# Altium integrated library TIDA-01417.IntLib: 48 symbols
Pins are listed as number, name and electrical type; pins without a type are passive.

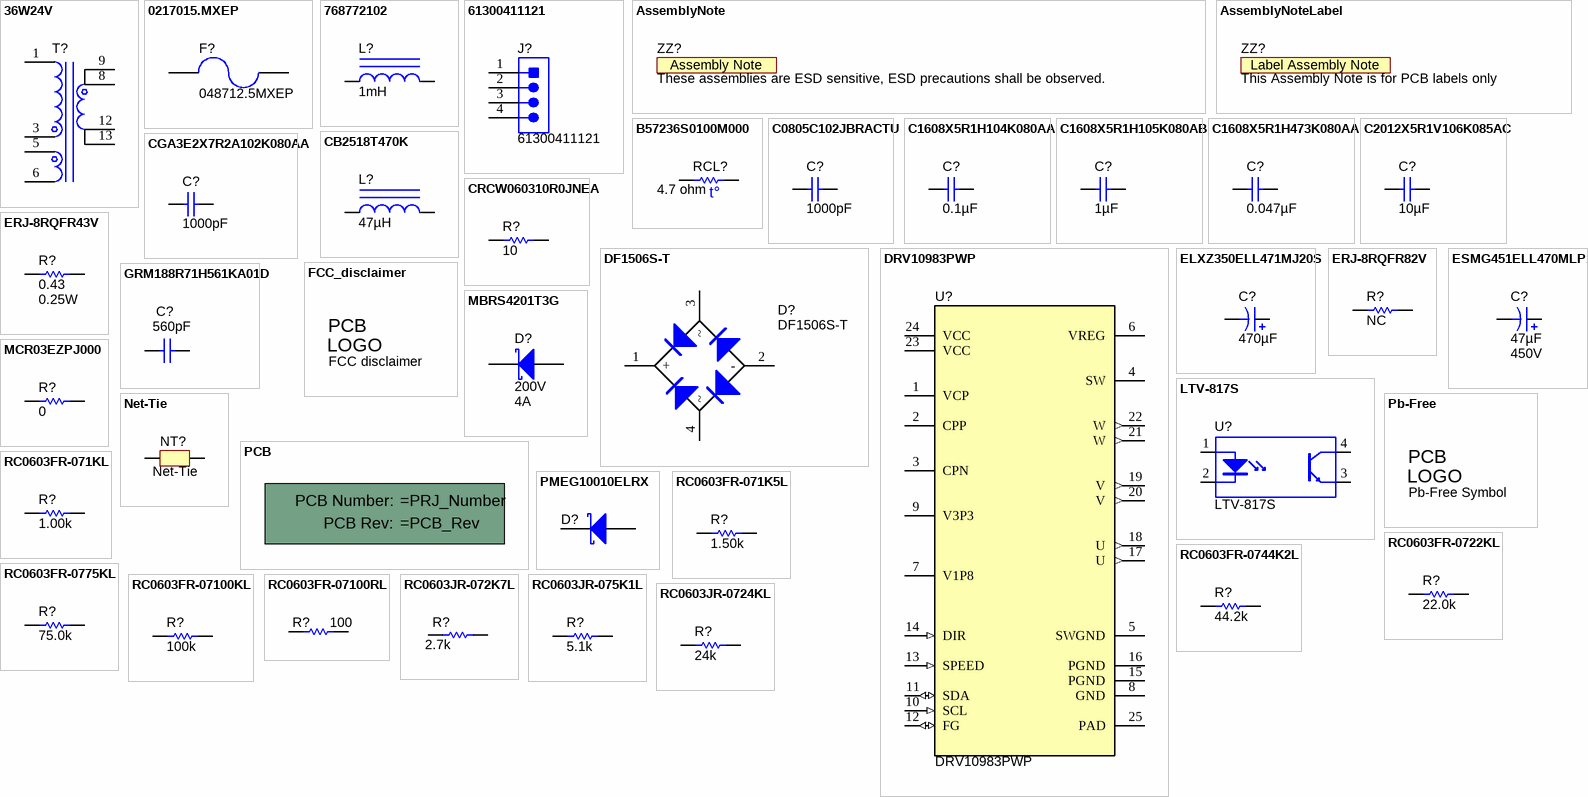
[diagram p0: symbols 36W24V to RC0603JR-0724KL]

## 36W24V
designator T?, comment Used in BOM report  (value not drawn)
SymbolVersion: use current date i.e. 2008-05-20; SymbolCreator: Use a-id; CompType: Used in some BOM reports.  Useful for finding later.; U/M: EA, IN, or GM
footprint PCBComponent_1
pins: 1, 3, 5, 6, 8, 9, 12, 13

## 0217015.MXEP
designator F?, comment 048712.5MXEP
FUSE 420VAC/DC 5X20 FA PT 12.5A; Manufacturer: Littelfuse; VDC_V: 250; Irating_A: 8; Rtyp_Ohm: 0.04; MeltingTyp: 617.135
footprint Fuse_217_015
footprint Fuse_217_015_Verical
pins: 1, 2

## 768772102
designator L?  ValueDisplayed: 1mH  (hidden comment: 768772102)
Inductor, Shielded Drum Core, Metal Composite, 1 mH, 0.5 A, 1.7 ohm, TH; Manufacturer: Wurth Elektronik; Value: 1mH; Ind_H: 1.0E-3; Imax_A: 0.5; Irms: 0.5A @ 40C rise; Isat: 0.55A @ 10% inductance drop; DCR_ohm: 1.7; Value1: 1.7 ohm; Value2: 0.5A; SizeAreaWB_mm2: 96.04; SizeArea_mm2: 60.84; SizeX_mm: 7.8; SizeZ_mm: 10; AEC Category: Q200
signal-integrity model Inductor
simulation model Inductor
footprint WE-TI_8095
pins: 1, 2

## 61300411121
designator J?
Header, 2.54 mm, 4x1, Gold, TH; Manufacturer: Wurth Elektronik; SymbolCreator: a0412235
footprint WURTH_61300411121
pins: 1, 2, 3, 4

## AssemblyNote
designator ZZ?, comment These assemblies are ESD sensitive, ESD precautions shall be observed.  (no BOM)
SymbolCreator: codlsc; CompType: AssemblyNote
footprint AssemblyNote

## AssemblyNoteLabel
designator ZZ?, comment This Assembly Note is for PCB labels only  (no BOM)
SymbolCreator: a0412235
footprint AssemblyNoteLabel

## B57236S0100M000
designator RCL?, comment value 4.7 ohm  (hidden comment: B57236S479M)
ICL 4.7 OHM 20% 4.6A 11.51MM; Manufacturer: EPCOS (TDK); CompType: ThermistorNTC; Tolerance_%: 20; Power_W: 2.1; U/M: EA; TaMin_C: -55; TaMax_C: 170
footprint THERM_B57236S0 (EPCOS)
pins: 1, 2

## C0805C102JBRACTU
designator C?  ValueDisplayed: 1000pF  (hidden comment: C0805C102JBRACTU)
CAP, CERM, 1000 pF, 630 V, +/- 5%, X7R, 0805; Manufacturer: Kemet; Polarized: N; CompType: Capacitor; Value: 1000pF; U/M: EA; Cap_F: 0.000000001; Tolerance_%: 5; Value1: Unknown; VDC_V: 630; Value2: 630V; TaMin_C: -55; TaMax_C: 125; Cap_Case: 0805; SizeArea_mm2: 2.5; SizeAreaWB_mm2: 6.75; SizeX_mm: 2; SizeY_mm: 1.25; SizeZ_mm: 1.45; AEC Category: Q200
signal-integrity model Cap
simulation model Cap
footprint 0805_HV
footprint 0805_HV1
footprint 0805
footprint 0805M
footprint 0805L
pins: 1, 2

## C1608X5R1H104K080AA
designator C?  ValueDisplayed: 0.1µF  (hidden comment: C1608X5R1H104K080AA)
CAP, CERM, 0.1 µF, 50 V, +/- 10%, X5R, 0603; Manufacturer: TDK; Polarized: N; CompType: Capacitor; Value: 0.1uF; U/M: EA; Cap_F: 0.0000001; Tolerance_%: 10; ESR_ohm: 0.0296; Value1: 0.0296 ohm; VDC_V: 50; Value2: 50V; IRMS_A: 0.97199; TaMin_C: -55; TaMax_C: 85; Cap_Case: 0603; SizeArea_mm2: 1.28; SizeAreaWB_mm2: 4.68; SizeX_mm: 1.6; SizeY_mm: 0.8; SizeZ_mm: 1; AEC Category: Q200
signal-integrity model Cap
simulation model Cap
footprint 0603
footprint 0603M
footprint 0603L
footprint 0603_HV
footprint 0603S
pins: 1, 2

## C1608X5R1H105K080AB
designator C?  ValueDisplayed: 1µF  (hidden comment: C1608X5R1H105K080AB)
CAP, CERM, 1 µF, 50 V, +/- 10%, X5R, 0603; Manufacturer: TDK; Polarized: N; CompType: Capacitor; Value: 1uF; U/M: EA; Cap_F: 0.000001; Tolerance_%: 10; ESR_ohm: 0.005522; Value1: 0.005522 ohm; VDC_V: 50; Value2: 50V; IRMS_A: 2.21617; TaMin_C: -55; TaMax_C: 85; Cap_Case: 0603; SizeArea_mm2: 1.28; SizeAreaWB_mm2: 4.68; SizeX_mm: 1.6; SizeY_mm: 0.8; SizeZ_mm: 1; AEC Category: Q200
signal-integrity model Cap
simulation model Cap
footprint 0603
footprint 0603M
footprint 0603L
footprint 0603_HV
footprint 0603S
pins: 1, 2

## C1608X5R1H473K080AA
designator C?  ValueDisplayed: 0.047µF  (hidden comment: C1608X5R1H473K080AA)
CAP, CERM, 0.047 µF, 50 V, +/- 10%, X5R, 0603; Manufacturer: TDK; Polarized: N; CompType: Capacitor; Value: 0.047uF; U/M: EA; Cap_F: 0.000000047; Tolerance_%: 10; ESR_ohm: 0.049007; Value1: 0.049007 ohm; VDC_V: 50; Value2: 50V; IRMS_A: 0.767528; TaMin_C: -55; TaMax_C: 85; Cap_Case: 0603; SizeArea_mm2: 1.28; SizeAreaWB_mm2: 4.68; SizeX_mm: 1.6; SizeY_mm: 0.8; SizeZ_mm: 1; AEC Category: Q200
signal-integrity model Cap
simulation model Cap
footprint 0603
footprint 0603M
footprint 0603L
footprint 0603_HV
footprint 0603S
pins: 1, 2

## C2012X5R1V106K085AC
designator C?  ValueDisplayed: 10µF  (hidden comment: C2012X5R1V106K085AC)
CAP, CERM, 10 µF, 35 V, +/- 10%, X5R, 0805; Manufacturer: TDK; Polarized: N; CompType: Capacitor; Value: 10uF; U/M: EA; Cap_F: 0.00001; Tolerance_%: 10; ESR_ohm: 0.002818; Value1: 0.002818 ohm; VDC_V: 35; Value2: 35V; IRMS_A: 3.88676; TaMin_C: -55; TaMax_C: 85; Cap_Case: 0805; SizeArea_mm2: 2.5; SizeAreaWB_mm2: 6.75; SizeX_mm: 2; SizeY_mm: 1.25; SizeZ_mm: 1.45; AEC Category: Q200
signal-integrity model Cap
simulation model Cap
footprint 0805_HV
footprint 0805_HV1
footprint 0805
footprint 0805M
footprint 0805L
pins: 1, 2

## CB2518T470K
designator L?  ValueDisplayed: 47µH  (hidden comment: CB2518T470K)
Inductor, Wirewound, Ferrite, 47 µH, 0.11 A, 1.235 ohm, SMD; Manufacturer: Taiyo Yuden; Value: 47uH; Ind_H: 47.0E-6; Imax_A: 0.11; Irms: 0.42A @ 40C rise; Isat: 0.11A @ 30% inductance drop; DCR_ohm: 1.235; Value2: 0.11A; SizeAreaWB_mm2: 9.8; SizeArea_mm2: 4.5; SizeX_mm: 2.5; SizeY_mm: 1.8; SizeZ_mm: 2; AEC Category: Q200
signal-integrity model Inductor
simulation model Inductor
footprint IND_CB2518
pins: 1, 2

## CGA3E2X7R2A102K080AA
designator C?  ValueDisplayed: 1000pF  (hidden comment: CGA3E2X7R2A102K080AA)
CAP, CERM, 1000 pF, 100 V, +/- 10%, X7R, AEC-Q200 Grade 1, 0603; Manufacturer: TDK; Polarized: N; CompType: Capacitor; Value: 1000pF; U/M: EA; Cap_F: 0.000000001; Tolerance_%: 10; ESR_ohm: 1.97137; Value1: 1.97137 ohm; VDC_V: 100; Value2: 100V; IRMS_A: 0.305705; TaMin_C: -55; TaMax_C: 125; Cap_Case: 0603; SizeArea_mm2: 1.28; SizeAreaWB_mm2: 4.68; SizeX_mm: 1.6; SizeY_mm: 0.8; SizeZ_mm: 1; AEC Category: Q200; AEC Qualified: Y
signal-integrity model Cap
simulation model Cap
footprint 0603
footprint 0603M
footprint 0603L
footprint 0603_HV
footprint 0603S
pins: 1, 2

## CRCW060310R0JNEA
designator R?  ValueDisplayed: 10  (hidden comment: CRCW060310R0JNEA)
RES, 10, 5%, 0.1 W, 0603; Manufacturer: Vishay-Dale; CompType: Resistor; Value: 10; Value_Code: 10R0; Tolerance_%: 5; Power_W: 0.1; Value2: 0.1W; VDC_V: 75; TempCo: 200 ppm/C; SizeArea_mm2: 1.28; SizeX_mm: 1.6; SizeY_mm: 0.8; SizeZ_mm: 1; EIA_Code: E24; U/M: EA; AEC Category: Q200
signal-integrity model Resistor
simulation model Resistor
footprint 0603
footprint 0603M
footprint 0603L
footprint 0603_HV
footprint 0603S
pins: 1, 2

## DF1506S-T
designator D?
Diode, Switching-Bridge, 600 V, 1.5 A, DF-S; Manufacturer: Diodes Inc.; U/M: EA; Vf_V: 1.1; Value: 600V; Value1: 1.5A; Value2: 1.1V; Io_A: 1.5; Vr_V: 600; TJmax_C: 150; SizeAreaWB_mm2: 98.794; SizeArea_mm2: 62.974; SizeX_mm: 7.4; SizeY_mm: 8.51; SizeZ_mm: 3.4; AEC Category: Q101
signal-integrity model Diode
simulation model DI_DF1506S
footprint DF-S
pins: 1 +, 2 -, 3 ~, 4 ~

## DRV10983PWP
designator U?
12- to 24-V, Three-Phase, Sensorless BLDC Motor Driver, PWP0024B (TSSOP-24); Manufacturer: Texas Instruments; SymbolCreator: a0411947; SizeArea_mm2: 49.92; SizeAreaWB_mm2: 82.32; SizeX_mm: 6.4; SizeY_mm: 7.8; SizeZ_mm: 1.2; CompType: IC; U/M: EA
footprint PWP0024B_N
footprint PWP0024B_M
footprint PWP0024B_L
footprint PWP0024B_NV_N
footprint PWP0024B_NV_M
footprint PWP0024B_NV_L
pins: 1 VCP (power), 2 CPP (power), 3 CPN (power), 4 SW (power), 5 SWGND (power), 6 VREG (power), 7 V1P8 (power), 8 GND (power), 9 V3P3 (power), 10 SCL (in), 11 SDA (io), 12 FG (io), 13 SPEED (in), 14 DIR (in), 15 PGND (power), 16 PGND (power), 17 U (out), 18 U (out), 19 V (out), 20 V (out), 21 W (out), 22 W (out), 23 VCC (power), 24 VCC (power), 25 PAD (power)

## ELXZ350ELL471MJ20S
designator C?  ValueDisplayed: 470µF  (hidden comment: ELXZ350ELL471MJ20S)
CAP, AL, 470 µF, 35 V, +/- 20%, AEC-Q200 Grade 2, TH; Manufacturer: Chemi-Con; Polarized: Y; CompType: Capacitor; Value: 470uF; U/M: EA; Cap_F: 0.00047; Tolerance_%: 20; Value1: Unknown; VDC_V: 35; Value2: 35V; IRMS_A: 1.22; TaMin_C: -55; TaMax_C: 105; Cap_Case: 10x20mm; SizeAreaWB_mm2: 144; SizeArea_mm2: 100; SizeX_mm: 10; SizeZ_mm: 21.5; AEC Category: Q200; AEC Grade: 2
signal-integrity model Cap
simulation model Cap
footprint Chemi-Con_1000x2000
pins: 1 +, 2 -

## ERJ-8RQFR43V
designator R?  ValueDisplayed: 0.43  Value2: 0.25W  (hidden comment: ERJ-8RQFR43V)
RES, 0.43, 1%, 0.25 W, AEC-Q200 Grade 1, 1206; Manufacturer: Panasonic; CompType: Resistor; Value: 0.43; Value_Code: R430; Tolerance_%: 1; Power_W: 0.25; TempCo: 250 ppm/C; SizeArea_mm2: 5.12; SizeX_mm: 3.2; SizeY_mm: 1.6; SizeZ_mm: 1.35; EIA_Code: E96; U/M: EA; AEC Category: Q200; AEC Qualified: Y
signal-integrity model Resistor
simulation model Resistor
footprint 1206
footprint 1206M
footprint 1206L
pins: 1, 2

## ERJ-8RQFR82V
designator R?, comment NC
RES, 0.82, 1%, 0.25 W, 1206; PartNumber: ERJ-8RQFR82V; Manufacturer: Panasonic; CompType: Resistor; Value: 0.82; Value_Code: R820; Tolerance_%: 1; Power_W: 0.25; Value2: 0.25W; TempCo: 250 ppm/C; SizeArea_mm2: 5.12; SizeX_mm: 3.2; SizeY_mm: 1.6; SizeZ_mm: 1.35; EIA_Code: E96; U/M: EA; AEC Category: Q200
signal-integrity model Resistor
simulation model Resistor
footprint 1206
footprint 1206M
footprint 1206L
pins: 1, 2

## ESMG451ELL470MLP1S
designator C?  ValueDisplayed: 47µF  Value2: 450V  (hidden comment: ESMG451ELL470MLP1S)
CAP, AL, 47 µF, 450 V, +/- 20%, TH; Manufacturer: Chemi-Con; Polarized: Y; CompType: Capacitor; Value: 47uF; U/M: EA; Cap_F: 0.000047; Tolerance_%: 20; Value1: Unknown; VDC_V: 450; IRMS_A: 0.265; TaMin_C: -25; TaMax_C: 85; Cap_Case: 16x35.5mm; SizeAreaWB_mm2: 324; SizeArea_mm2: 256; SizeX_mm: 16; SizeZ_mm: 37; AEC Category: Q200; AEC Qualified: N
signal-integrity model Cap
simulation model Cap
footprint SMG_1600x3550
pins: 1 +, 2 -

## FCC_disclaimer
designator Logo?, comment FCC disclaimer  (no BOM)
FCC_disclaimer; SymbolCreator: codlsc
footprint FCC_disclaimer
footprint FCC_disclaimer_stacked

## GRM188R71H561KA01D
designator C?  ValueDisplayed: 560pF  (hidden comment: GRM188R71H561KA01D)
CAP, CERM, 560 pF, 50 V, +/- 10%, X7R, 0603; Manufacturer: MuRata; Polarized: N; CompType: Capacitor; Value: 560pF; U/M: EA; Cap_F: 0.00000000056; Tolerance_%: 10; Value1: Unknown; VDC_V: 50; Value2: 50V; TaMin_C: -55; TaMax_C: 125; Cap_Case: 0603; SizeArea_mm2: 1.28; SizeAreaWB_mm2: 4.68; SizeX_mm: 1.6; SizeY_mm: 0.8; SizeZ_mm: 1; AEC Category: Q200
signal-integrity model Cap
simulation model Cap
footprint 0603
footprint 0603M
footprint 0603L
footprint 0603_HV
footprint 0603S
pins: 1, 2

## LTV-817S
designator U?
Optocoupler, 5 kV, 50-600% CTR, SMT; Manufacturer: Lite-On; CTR (Min): 50%; CTR (Max): 600%; Voltage_Isolation_Vrms: 5000V; SizeAreaWB_mm2: 80.256; SizeArea_mm2: 46.736; SizeX_mm: 10.16; SizeY_mm: 4.6
footprint DIP254P762X350-4
pins: 1 A, 2 K, 3 E, 4 C
1 alternate drawing of the same symbol

## MBRS4201T3G
designator D?  value 200V  Value1: 4A  (hidden comment: MBRS4201T3G)
Diode, Schottky, 200 V, 4 A, SMC; Manufacturer: ON Semiconductor; U/M: EA; Vf_V: 0.86; Value2: 0.86V; Io_A: 4; Vr_V: 200; TJmax_C: 150; SizeAreaWB_mm2: 83.2686; SizeArea_mm2: 50.5686; SizeX_mm: 8.13; SizeY_mm: 6.22; SizeZ_mm: 2.6; AEC Category: Q101
signal-integrity model Diode
footprint SMC
pins: 1 K, 2 A

## MCR03EZPJ000
designator R?  ValueDisplayed: 0  (hidden comment: MCR03EZPJ000)
RES, 0, 5%, 0.1 W, 0603; Manufacturer: Rohm; CompType: Resistor; Value: 0; Value_Code: 0000; Tolerance_%: 5; Power_W: 0.1; Value2: 0.1W; TempCo: ppm/C; SizeArea_mm2: 1.28; SizeX_mm: 1.6; SizeY_mm: 0.8; SizeZ_mm: 1; EIA_Code: E24; U/M: EA; AEC Category: Q200; AEC Qualified: N
signal-integrity model Resistor
simulation model Resistor
footprint 0603
footprint 0603M
footprint 0603L
footprint 0603_HV
footprint 0603S
pins: 1, 2

## Net-Tie
designator NT?  (net tie, no BOM)
Single point connection between nets.; SymbolCreator: codlsc
footprint Net-Tie_10mil (10mil net tie, no solder mask opening, no solder paste)
footprint NetTie_1206 (1206 pads tied by 10mil copper trace which can be cut.  Part can be placed on pads.)
footprint Net-Tie_0805_HV
footprint NetTie_1206_NoOverlay (1206 pads tied by 10mil copper trace which can be cut.  Part can be placed on pads.)
footprint Net-Tie_0805_HV_NoOverlay (0805_HV pads tied by 10mil copper trace which can be cut.  An 0805 part can be placed on pads.)
footprint Net-Tie_10milWide_30milLong
footprint Net-Tie_20milWide_60milLong
footprint NetTie_0603
footprint NetTie_0402
footprint Net-Tie_50milWide_30milLong
pins: 1, 2

## Pb-Free
designator Logo?, comment Pb-Free Symbol  (no BOM)
SymbolCreator: a0412235
footprint Pb-Free_Overlay_Medium
footprint Pb-Free_Overlay_Small

## PCB
designator !PCB?, comment Printed Circuit Board  (value not drawn)  (mechanical)
Manufacturer: Any; SymbolCreator: a0412235; CompType: PCB
1 alternate drawing of the same symbol

## PMEG10010ELRX
designator D?  (value not drawn)
Diode, Schottky, 100 V, 1 A, AEC-Q101, SOD-123W; Manufacturer: NXP Semiconductor; U/M: EA; Vf_V: 0.77; Value: 100V; Value1: 1A; Value2: 0.77V; Io_A: 1; Vr_V: 100; TJmax_C: 175; SizeAreaWB_mm2: 12.15; SizeArea_mm2: 5.95; SizeX_mm: 3.5; SizeY_mm: 1.7; AEC Category: Q101; AEC Qualified: Y
signal-integrity model Diode
footprint SOD-123W
pins: 1 K, 2 A

## RC0603FR-071K5L
designator R?  ValueDisplayed: 1.50k  (hidden comment: RC0603FR-071K5L)
RES, 1.50 k, 1%, 0.1 W, 0603; Manufacturer: Yageo America; CompType: Resistor; Value: 1.50k; Res_ohm: 1500; Value_Code: 1k50; Tolerance_%: 1; Power_W: 0.1; Value2: 0.1W; VDC_V: 150; TempCo: 200 ppm/C; SizeArea_mm2: 1.28; SizeX_mm: 1.6; SizeY_mm: 0.8; EIA_Code: E96; U/M: EA; AEC Category: Q200
signal-integrity model Resistor
simulation model Resistor
footprint 0603
footprint 0603M
footprint 0603L
footprint 0603_HV
footprint 0603S
pins: 1, 2

## RC0603FR-071KL
designator R?  ValueDisplayed: 1.00k  (hidden comment: RC0603FR-071KL)
RES, 1.00 k, 1%, 0.1 W, 0603; Manufacturer: Yageo America; CompType: Resistor; Value: 1.00k; Res_ohm: 1000; Value_Code: 1k00; Tolerance_%: 1; Power_W: 0.1; Value2: 0.1W; VDC_V: 150; TempCo: 200 ppm/C; SizeArea_mm2: 1.28; SizeX_mm: 1.6; SizeY_mm: 0.8; EIA_Code: E96; U/M: EA; AEC Category: Q200
signal-integrity model Resistor
simulation model Resistor
footprint 0603
footprint 0603M
footprint 0603L
footprint 0603_HV
footprint 0603S
pins: 1, 2

## RC0603FR-0722KL
designator R?  ValueDisplayed: 22.0k  (hidden comment: RC0603FR-0722KL)
RES, 22.0 k, 1%, 0.1 W, 0603; Manufacturer: Yageo America; CompType: Resistor; Value: 22.0k; Res_ohm: 22000; Value_Code: 22k0; Tolerance_%: 1; Power_W: 0.1; Value2: 0.1W; VDC_V: 150; TempCo: 200 ppm/C; SizeArea_mm2: 1.28; SizeX_mm: 1.6; SizeY_mm: 0.8; U/M: EA; AEC Category: Q200
signal-integrity model Resistor
simulation model Resistor
footprint 0603
footprint 0603M
footprint 0603L
footprint 0603_HV
footprint 0603S
pins: 1, 2

## RC0603FR-0744K2L
designator R?  ValueDisplayed: 44.2k  (hidden comment: RC0603FR-0744K2L)
RES, 44.2 k, 1%, 0.1 W, 0603; Manufacturer: Yageo America; CompType: Resistor; Value: 44.2k; Res_ohm: 44200; Value_Code: 44k2; Tolerance_%: 1; Power_W: 0.1; Value2: 0.1W; VDC_V: 150; TempCo: 200 ppm/C; SizeArea_mm2: 1.28; SizeX_mm: 1.6; SizeY_mm: 0.8; EIA_Code: E96; U/M: EA; AEC Category: Q200
signal-integrity model Resistor
simulation model Resistor
footprint 0603
footprint 0603M
footprint 0603L
footprint 0603_HV
footprint 0603S
pins: 1, 2

## RC0603FR-0775KL
designator R?  ValueDisplayed: 75.0k  (hidden comment: RC0603FR-0775KL)
RES, 75.0 k, 1%, 0.1 W, 0603; Manufacturer: Yageo America; CompType: Resistor; Value: 75.0k; Res_ohm: 75000; Value_Code: 75k0; Tolerance_%: 1; Power_W: 0.1; Value2: 0.1W; VDC_V: 150; TempCo: 200 ppm/C; SizeArea_mm2: 1.28; SizeX_mm: 1.6; SizeY_mm: 0.8; EIA_Code: E96; U/M: EA; AEC Category: Q200
signal-integrity model Resistor
simulation model Resistor
footprint 0603
footprint 0603M
footprint 0603L
footprint 0603_HV
footprint 0603S
pins: 1, 2

## RC0603FR-07100KL
designator R?  ValueDisplayed: 100k  (hidden comment: RC0603FR-07100KL)
RES, 100 k, 1%, 0.1 W, 0603; Manufacturer: Yageo America; CompType: Resistor; Value: 100k; Res_ohm: 100000; Tolerance_%: 1; Power_W: 0.1; Value2: 0.1W; VDC_V: 150; TempCo: 200 ppm/C; SizeArea_mm2: 1.28; SizeX_mm: 1.6; SizeY_mm: 0.8; EIA_Code: E96; U/M: EA; AEC Category: Q200
signal-integrity model Resistor
simulation model Resistor
footprint 0603
footprint 0603M
footprint 0603L
footprint 0603_HV
footprint 0603S
pins: 1, 2

## RC0603FR-07100RL
designator R?  ValueDisplayed: 100  (hidden comment: RC0603FR-07100RL)
RES, 100, 1%, 0.1 W, 0603; Manufacturer: Yageo America; CompType: Resistor; Value: 100; Value_Code: 100R; Tolerance_%: 1; Power_W: 0.1; Value2: 0.1W; VDC_V: 150; TempCo: 200 ppm/C; SizeArea_mm2: 1.28; SizeX_mm: 1.6; SizeY_mm: 0.8; EIA_Code: E96; U/M: EA; AEC Category: Q200
signal-integrity model Resistor
simulation model Resistor
footprint 0603
footprint 0603M
footprint 0603L
footprint 0603_HV
footprint 0603S
pins: 1, 2

## RC0603JR-072K7L
designator R?  ValueDisplayed: 2.7k  (hidden comment: RC0603JR-072K7L)
RES, 2.7 k, 5%, 0.1 W, 0603; Manufacturer: Yageo America; CompType: Resistor; Value: 2.7k; Res_ohm: 2700; Value_Code: 2k70; Tolerance_%: 5; Power_W: 0.1; Value2: 0.1W; VDC_V: 50; TempCo: 100 ppm/C; SizeArea_mm2: 1.28; SizeX_mm: 1.6; SizeY_mm: 0.8; SizeZ_mm: 1; EIA_Code: E24; U/M: EA; AEC Category: Q200
signal-integrity model Resistor
simulation model Resistor
footprint 0603
footprint 0603M
footprint 0603L
footprint 0603_HV
footprint 0603S
pins: 1, 2

## RC0603JR-075K1L
designator R?  ValueDisplayed: 5.1k  (hidden comment: RC0603JR-075K1L)
RES, 5.1 k, 5%, 0.1 W, 0603; Manufacturer: Yageo America; CompType: Resistor; Value: 5.1k; Res_ohm: 5100; Value_Code: 5k10; Tolerance_%: 5; Power_W: 0.1; Value2: 0.1W; VDC_V: 50; TempCo: 100 ppm/C; SizeArea_mm2: 1.28; SizeX_mm: 1.6; SizeY_mm: 0.8; SizeZ_mm: 1; EIA_Code: E24; U/M: EA; AEC Category: Q200
signal-integrity model Resistor
simulation model Resistor
footprint 0603
footprint 0603M
footprint 0603L
footprint 0603_HV
footprint 0603S
pins: 1, 2

## RC0603JR-0724KL
designator R?  ValueDisplayed: 24k  (hidden comment: RC0603JR-0724KL)
RES, 24 k, 5%, 0.1 W, 0603; Manufacturer: Yageo America; CompType: Resistor; Value: 24k; Res_ohm: 24000; Value_Code: 24k0; Tolerance_%: 5; Power_W: 0.1; Value2: 0.1W; VDC_V: 50; TempCo: 100 ppm/C; SizeArea_mm2: 1.28; SizeX_mm: 1.6; SizeY_mm: 0.8; SizeZ_mm: 1; EIA_Code: E24; U/M: EA; AEC Category: Q200
signal-integrity model Resistor
simulation model Resistor
footprint 0603
footprint 0603M
footprint 0603L
footprint 0603_HV
footprint 0603S
pins: 1, 2

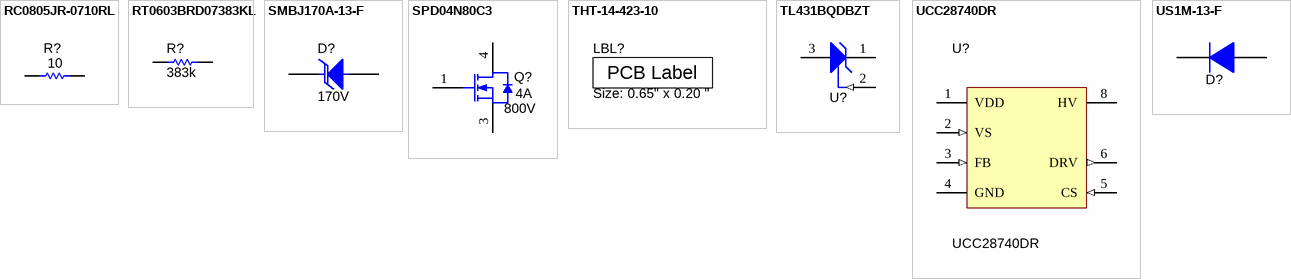
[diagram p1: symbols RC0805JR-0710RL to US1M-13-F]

## RC0805JR-0710RL
designator R?  ValueDisplayed: 10  (hidden comment: RC0805JR-0710RL)
RES, 10, 5%, 0.125 W, 0805; Manufacturer: Yageo America; CompType: Resistor; Value: 10; Value_Code: 10R0; Tolerance_%: 5; Power_W: 0.125; Value2: 0.125W; VDC_V: 150; TempCo: 200 ppm/C; SizeArea_mm2: 2.5; SizeX_mm: 2; SizeY_mm: 1.25; SizeZ_mm: 1.45; EIA_Code: E24; U/M: EA; AEC Category: Q200
signal-integrity model Resistor
simulation model Resistor
footprint 0805_HV
footprint 0805_HV1
footprint 0805
footprint 0805M
footprint 0805L
pins: 1, 2

## RT0603BRD07383KL
designator R?  ValueDisplayed: 383k  (hidden comment: RT0603BRD07383KL)
RES, 383 k, 0.1%, 0.1 W, 0603; Manufacturer: Yageo America; CompType: Resistor; Value: 383k; Res_ohm: 383000; Tolerance_%: 0.1; Value2: 0.1W; VDC_V: 75; TempCo: 25 ppm/C; SizeArea_mm2: 1.28; SizeX_mm: 1.6; SizeY_mm: 0.8; SizeZ_mm: 1; EIA_Code: E192; U/M: EA; AEC Category: Q200
signal-integrity model Resistor
simulation model Resistor
footprint 0603
footprint 0603M
footprint 0603L
footprint 0603_HV
footprint 0603S
pins: 1, 2

## SMBJ170A-13-F
designator D?  value 170V  (hidden comment: SMBJ170A-13-F)
Diode, TVS, Uni, 170 V, 275 Vc, SMB; Manufacturer: Diodes Inc.; U/M: EA; Power_W: 5; Vr_V: 170; Value1: 5W; SizeAreaWB_mm2: 44.156; SizeArea_mm2: 21.336; SizeX_mm: 5.6; SizeY_mm: 3.81; SizeZ_mm: 2.6; AEC Category: Q101
footprint SMB
pins: 1 K, 2 A

## SPD04N80C3
designator Q?  value 800V  IdsMax_A: 4A  (hidden comment: SPD04N80C3)
MOSFET, N-CH, 800 V, 4 A, DPAK; Manufacturer: Infineon Technologies; Alternate Manufacturer: None; U/M: EA; ChType: N; VdsMax_V: 800; Value1: 1.3 ohm; Rdson45_ohm: 1.3; Value2: 26 nC; QgTyp_nC: 26; Vgs_V: 3.9; SizeAreaWB_mm2: 101.7114; SizeArea_mm2: 64.8114; SizeX_mm: 9.91; SizeY_mm: 6.54; SizeZ_mm: 2.29; AEC Category: Q101
footprint DPAK
pins: 1 G, 3 S, 4 D

## THT-14-423-10
designator LBL?, comment Size: 0.65" x 0.20 "
Thermal Transfer Printable Labels, 0.650" W x 0.200" H - 10,000 per roll; Manufacturer: Brady; PartNumber: THT-14-423-10; SymbolCreator: a0412235; CompType: Label
footprint Label_650x200

## TL431BQDBZT
designator U?  (value not drawn)
Adjustable Precision Shunt Regulator, 34 ppm / degC, 100 mA, -40 to 125 degC, 3-pin SOT-23 (DBZ), Green (RoHS & no Sb/Br); Manufacturer: Texas Instruments; Alternate PartNumber: Equivalent; Initial Accuracy @ 25/deg C(%): 0.5; Iout/Iz(Max)(mA): 100; Min Iz for Regulation(uA): 600; Rating: Catalog; SubFamily: Shunt Voltage Reference; Temp Coeff(Max)(ppm/ degree C): 92; Temp Coeff(Typ)(ppm/ degree C): 34; VO Adj(Max)(V): 36; VO Adj(Min)(V): 2.495
footprint DBZ0003A_N (SOT23, 3-Leads, Body 2.92x1.3 mm, Pitch 0.95 mm, IPC Medium Density)
footprint DBZ0003A_L (SOT23, 3-Leads, Body 2.92x1.3 mm, Pitch 0.95 mm, IPC High Density)
footprint DBZ0003A_M (SOT23, 3-Leads, Body 2.92x1.3 mm, Pitch 0.95 mm, IPC Low Density)
pins: 1 CATHODE, 2 REF (in), 3 ANODE

## UCC28740DR
designator U?
Constant-Voltage, Constant-Current Flyback Controller Using Opto-Coupler Feedback, D0007A (SOIC-7); Manufacturer: Texas Instruments; SymbolCreator: a0412235; SizeArea_mm2: 29.4; SizeAreaWB_mm2: 55.2; SizeX_mm: 6; SizeY_mm: 4.9; SizeZ_mm: 1.75; CompType: IC; U/M: EA
footprint D0007A_N
footprint D0007A_M
footprint D0007A_L
pins: 1 VDD (power), 2 VS (in), 3 FB (in), 4 GND (power), 5 CS (in), 6 DRV (out), 8 HV (power)
1 alternate drawing of the same symbol

## US1M-13-F
designator D?  (value not drawn)
Diode, Ultrafast, 1000 V, 1 A, SMA; Manufacturer: Diodes Inc.; U/M: EA; Vf_V: 1.7; Value: 1000V; Value1: 1A; Value2: 1.7V; Io_A: 1; Vr_V: 1000; TJmax_C: 150; RJC_CperW: 30; SizeAreaWB_mm2: 37.3428; SizeArea_mm2: 16.3228; SizeX_mm: 5.59; SizeY_mm: 2.92; SizeZ_mm: 2.87; AEC Category: Q101
signal-integrity model Diode
footprint SMA
pins: 1 K, 2 A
